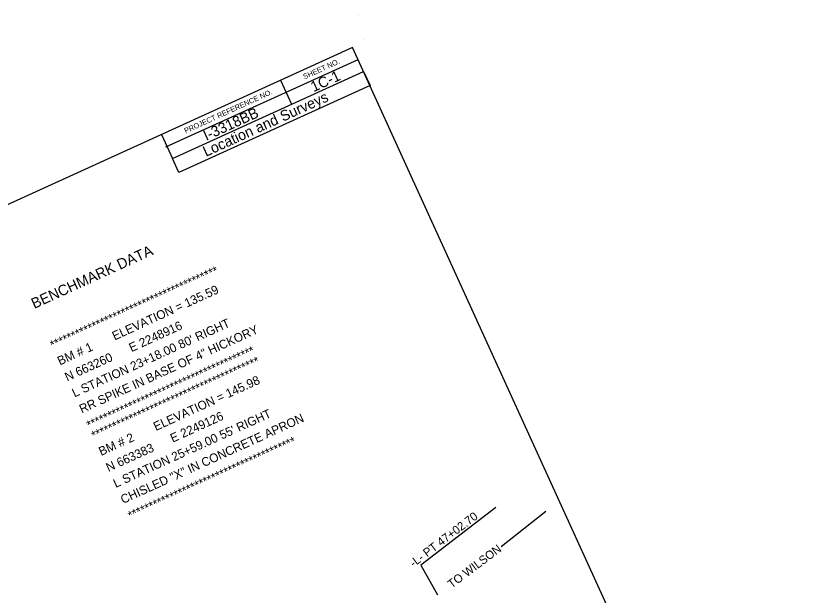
# Model space of a CAD drawing. Extents: x 2243531 to 2252747, y 658714 to 667210.
# Drawn here: x 2248974 to 2252747, y 664466 to 667210 of the extents above; entities that cross this region are included whole.
import ezdxf

# ---------------------------------------------------------------- set-up
doc = ezdxf.new("R2010")
doc.units = 0
for name, color, linetype in [('CTL Sheet Border CELL', 7, 'Continuous'), ('CTL Sheet Text', 7, 'Continuous'), ('Exist Roads EOP Leader', 7, 'Continuous'), ('Exist Roads EOP Text', 7, 'Continuous')]:
    doc.layers.add(name, color=color, linetype=linetype)

msp = doc.modelspace()

# ---------------------------------------------------------------- linework, layer by layer
at = {"layer": 'CTL Sheet Border CELL'}
for p, q in [((2250595.2, 667210), (2250595.2, 667210)), ((2250621.3, 667098.6), (2250621.3, 667098.6)), ((2250621.3, 667098.6), (2250621.3, 667098.6)), ((2249685.4, 666589.1), (2250595.7, 667003.9)), ((2250228.5, 666905.3), (2250280.4, 666791.6)), ((2249664.7, 666648.4), (2249716.5, 666534.7))]:
    msp.add_line(p, q, dxfattribs=at)
for points in [[(2250569.7, 667061), (2243744.8, 663951.1), (2245921.8, 659173.7), (2252746.6, 662283.7)], [(2249716.5, 666534.7), (2250621.6, 666947.1), (2250652.1, 666880.1), (2249747, 666467.7)]]:
    msp.add_lwpolyline(points, close=True, dxfattribs=at)
at = {"layer": 'Exist Roads EOP Leader'}
msp.add_line((2251485.4, 664862.4), (2251273.9, 664694), dxfattribs=at)
at = {"layer": 'Exist Roads EOP Text'}
msp.add_lwpolyline([(2251249, 664881.4), (2250892.5, 664608.3), (2250972, 664466.4)], dxfattribs=at)

# ---------------------------------------------------------------- texts
at = {"layer": 'CTL Sheet Border CELL'}
for s, height, p in [('SHEET NO.', 25, (2250342, 666908.9)), ('1C-1', 50, (2250384.9, 666848.4)), ('PROJECT REFERENCE NO.', 25, (2249778.6, 666652.7)), ('Location and Surveys', 50.001, (2249874.6, 666541.7)), ('I-3318BB', 50, (2249876, 666617.5)), ('BENCHMARK DATA', 50.001, (2249061.2, 665821.4))]:
    msp.add_text(s, height=height, rotation=24.4979, dxfattribs=at).set_placement(p)
at = {"layer": 'CTL Sheet Text'}
for s, p in [('****************************************', (2249148.2, 665629.5)), ('BM # 1       ELEVATION = 135.59', (2249182.7, 665553.7)), ('N 663260      E 2248916', (2249217.3, 665477.8)), ("L STATION 23+18.00 80' RIGHT", (2249251.8, 665402)), ('RR SPIKE IN BASE OF 4" HICKORY', (2249286.4, 665326.2)), ('****************************************', (2249321, 665250.3)), ('****************************************', (2249343.6, 665200.5)), ('BM # 2       ELEVATION = 145.98', (2249378.2, 665124.7)), ("L STATION 25+59.00 55' RIGHT", (2249447.3, 664973.1)), ('N 663383      E 2249126', (2249412.8, 665048.9)), ('CHISLED "X" IN CONCRETE APRON', (2249481.9, 664897.2)), ('****************************************', (2249516.4, 664821.4))]:
    msp.add_text(s, height=41.667, rotation=24.4979, dxfattribs=at).set_placement(p)
at = {"layer": 'Exist Roads EOP Text'}
for s, rotation, p in [('-L- PT 47+02.70', 37.3381, (2250858.6, 664595.8)), ('TO WILSON', 37.0386, (2251039.1, 664495.9))]:
    msp.add_text(s, height=40, rotation=rotation, dxfattribs=at).set_placement(p)

doc.saveas('drawing.dxf')
